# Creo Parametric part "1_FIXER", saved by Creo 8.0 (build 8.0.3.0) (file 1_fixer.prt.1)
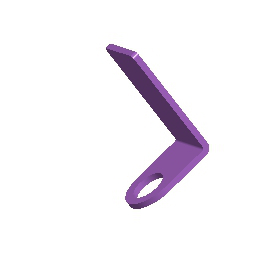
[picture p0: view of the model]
Units: millimeter Newton Second (mmNs); MM, TONNE, SECS

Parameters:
  SMT_DFLT_BEND_REL_LENGTH_TYPE = "Through All"

Other parameters: SMT_UPDATE_BEND_ALLOW_INFO, SMT_THICKNESS, SMT_PART_BEND_ALLOWANCE_FACTOR, SMT_DFLT_BEND_RADIUS, SMT_DFLT_BEND_ANGLE, SMT_DFLT_CRNR_REL_WIDTH, SMT_DFLT_CRNR_REL_DEPTH, SMT_DFLT_BEND_REL_WIDTH, SMT_DFLT_BEND_REL_DEPTH, SMT_DFLT_BEND_REL_LENGTH, SMT_DFLT_BEND_REL_ANGLE, SMT_GAP, SMT_DFLT_EDGE_TREA_WIDTH, SMT_DFLT_MITER_CUT_WIDTH, SMT_DFLT_MITER_CUT_OFFSET

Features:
  1. datum plane "RIGHT"
  2. datum plane "TOP"
  3. datum plane "FRONT"
  4. coordinate system
  5. round
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
Layers: 0_ALL_AXIS, 0_ALL_CSYS, 0_ALL_CURVES, 0_ALL_PLANES, 0_ALL_POINTS, 0_ALL_SURFS, FIXER

Surfaces: 11 plane, 6 cylinder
